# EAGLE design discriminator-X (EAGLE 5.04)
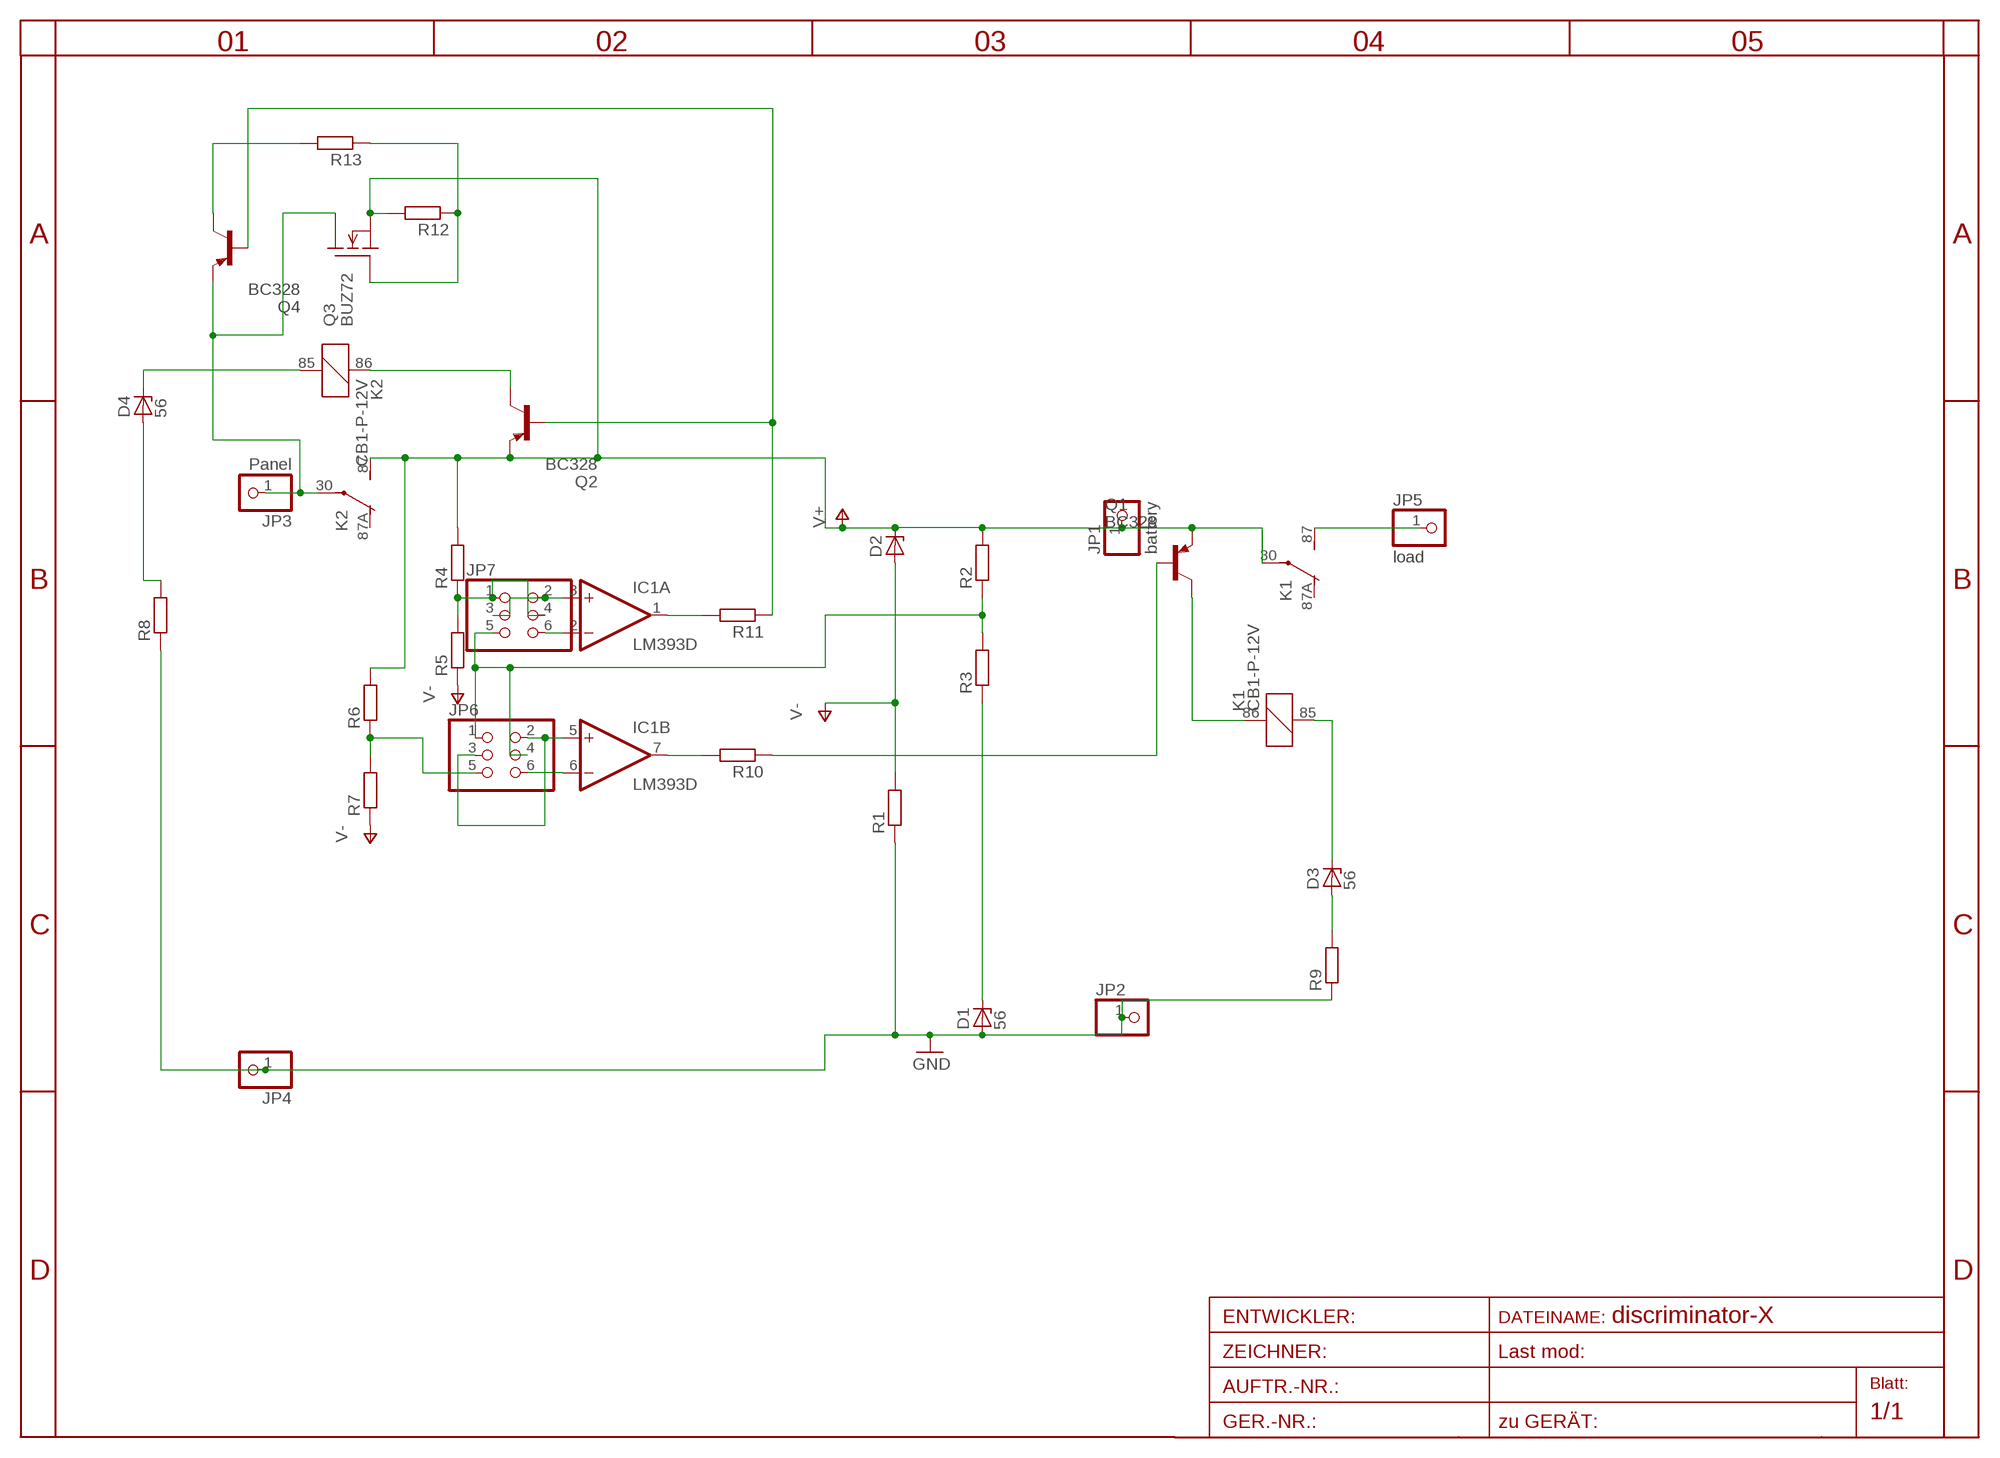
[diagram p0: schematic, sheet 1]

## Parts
D1  56  ZENER-DIODEDO35Z10  [DO35Z10]
D2  ZENER-DIODEDO35Z10  [DO35Z10]
D3  56  ZENER-DIODEDO35Z10  [DO35Z10]
D4  56  ZENER-DIODEDO35Z10  [DO35Z10]
IC1  LM393D  [SO08]
JP1  battery  PINHD-1X1  [1X01]
JP2  PINHD-1X1  [1X01]
JP3  Panel  PINHD-1X1  [1X01]
JP4  PINHD-1X1  [1X01]
JP5  load  PINHD-1X1  [1X01]
JP6  PINHD-2X3  [2X03]
JP7  PINHD-2X3  [2X03]
K1  CB1-P-12V  [CB1]
K2  CB1-P-12V  [CB1]
Q1  BC328  [TO92-EBC]
Q2  BC328  [TO92-EBC]
Q3  BUZ72  [TO220]
Q4  BC328  [TO92-EBC]
R1  R-EU_0204/7  [0204/7]
R2  R-EU_0204/7  [0204/7]
R3  R-EU_0204/7  [0204/7]
R4  R-EU_0204/7  [0204/7]
R5  R-EU_0204/7  [0204/7]
R6  R-EU_0204/7  [0204/7]
R7  R-EU_0204/7  [0204/7]
R8  R-EU_0204/7  [0204/7]
R9  R-EU_0204/7  [0204/7]
R10  R-EU_0204/7  [0204/7]
R11  R-EU_0204/7  [0204/7]
R12  R-EU_0204/7  [0204/7]
R13  R-EU_0204/7  [0204/7]

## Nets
GND: D1.A JP2.1 JP4.1 R1.1 R8.1 R9.1
LOAD: JP5.1 K1.87(2:S)
N$1: D1.C R3.1
N$2: IC1.3(A:+IN) JP7.2 JP7.3
N$3: IC1.5(B:+IN) JP6.2 JP6.3
N$4: JP6.1 JP6.4 JP7.5 R2.1 R3.2
N$5: K1.86 Q1.C
N$6: D3.C K1.85
N$7: D3.A R9.2
N$8: K2.86 Q2.C
N$9: D4.C K2.85
N$10: D4.A R8.2
N$11: IC1.6(B:-IN) JP6.6
N$12: JP6.5 R6.1 R7.2
N$13: JP7.1 JP7.4 R4.1 R5.2
N$14: IC1.1(A:OUT) R11.2
N$15: IC1.7(B:OUT) R10.2
N$16: Q2.B Q4.B R11.1
N$17: Q1.B R10.1
N$19: Q3.1(G) R12.1 R13.1
N$20: Q4.C R13.2
N$22: IC1.2(A:-IN) JP7.6
PANEL: JP3.1 K2.30(2:P) Q3.2(D) Q4.E
V+: D2.C JP1.1 K1.30(2:P) K2.87(2:S) Q1.E Q2.E Q3.3(S) R2.2 R4.2 R6.2 R12.2
V-: D2.A R1.2 R5.1 R7.1
Unconnected: K1.87A(2:O) K2.87A(2:O)

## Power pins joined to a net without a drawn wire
V+: IC1.8(P:V+)
V-: IC1.4(P:V-)

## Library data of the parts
D1-D4 = diode-1:ZENER-DIODE: Z-Diode
IC1 = linear:LM393: COMPARATOR
JP1-JP5 = pinhead:PINHD-1X1: PIN HEADER
JP6 JP7 = pinhead(2):PINHD-2X3: PIN HEADER
K1 K2 = relay:CB1*: HIGH POWER AUTOMOTIVE RELAY Form C NAiS Source: http://www.mew-europe.com/.. en_ds_61202_0000.pdf
Q1 Q2 Q4 = transistor-pnp:BC328*: PNP Transistror
Q3 = transistor-fet:BUZ72: N-Channel Enhancement MOSFET 100V; 10A; 0,2Ohm
R1-R13 = rcl-2:R-EU_: RESISTOR, European symbol

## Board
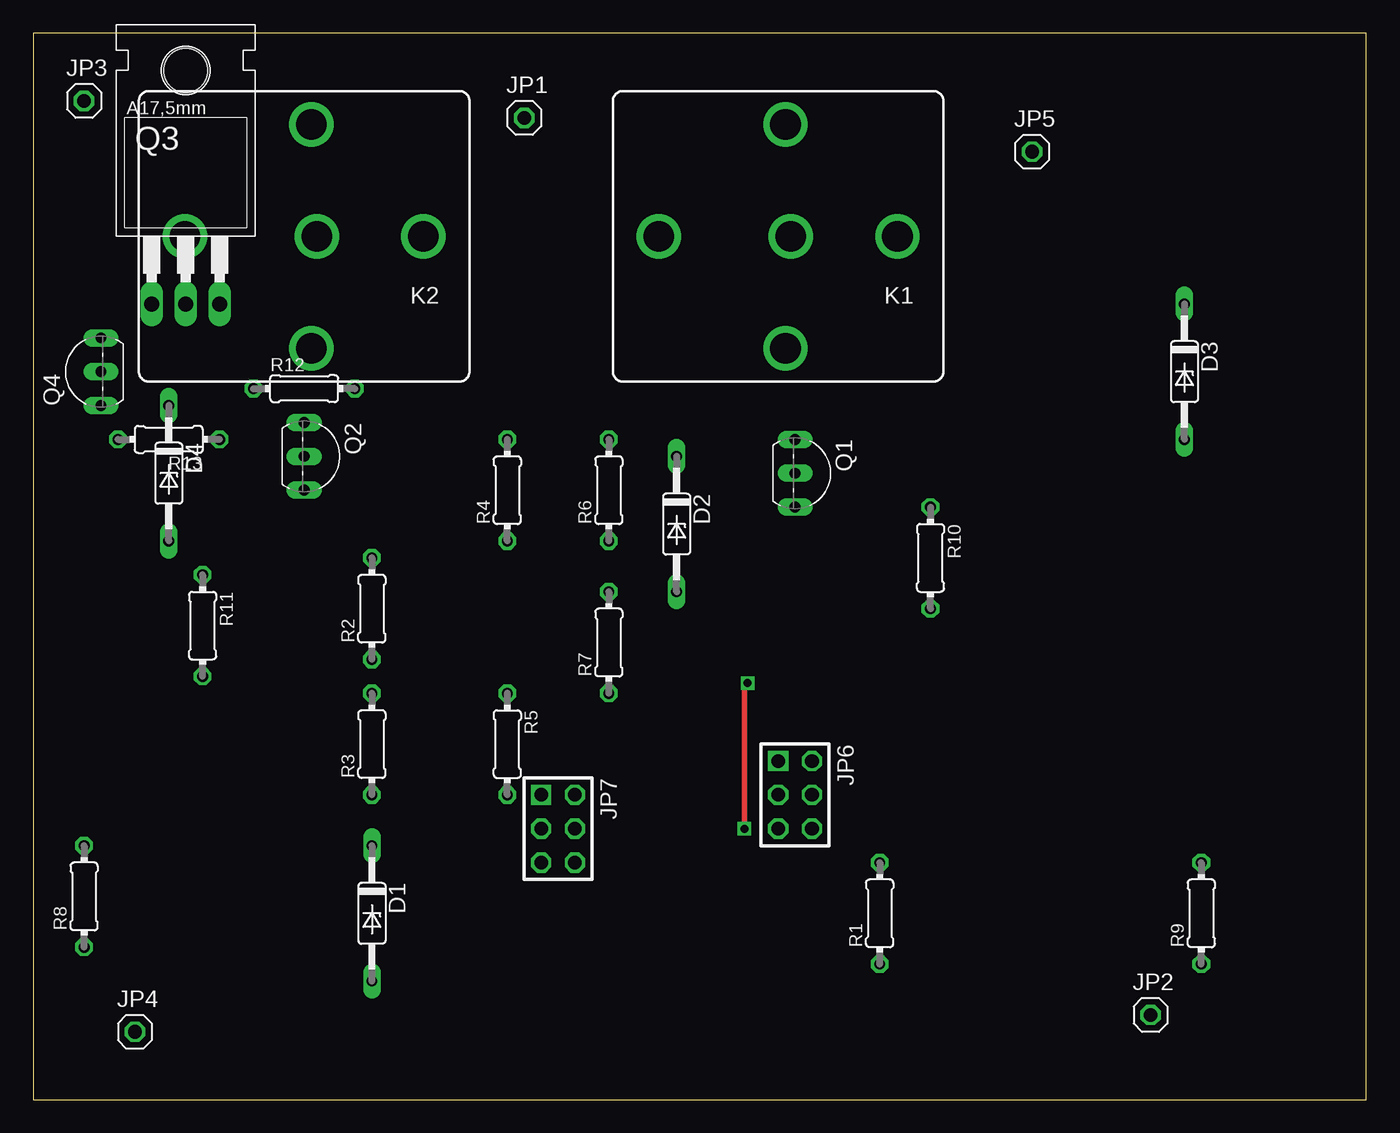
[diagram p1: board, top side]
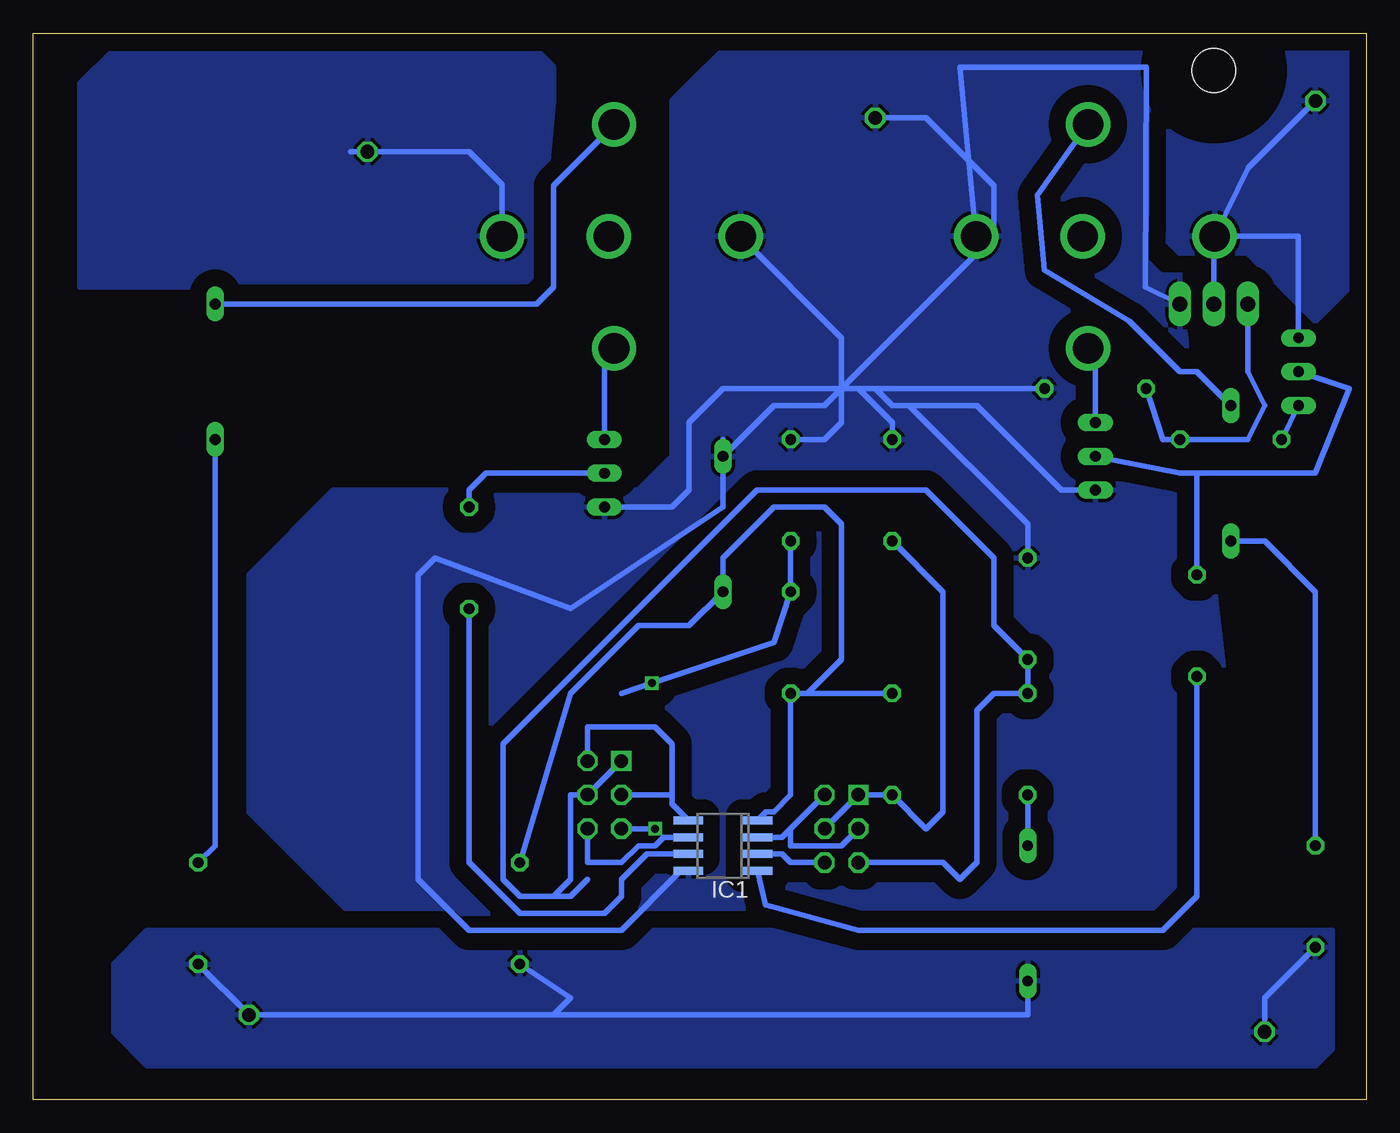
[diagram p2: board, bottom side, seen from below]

Size 100 x 80 mm. Coordinates in mm from the lower left corner, seen from the top.
Outline: 0,0 100,0 100,80 0,80 0,0
Copper layers (1*16): Top 0.035mm / dielectric 1.5mm / Bottom 0.035mm
Design rules "default": minimum track width 10mil, minimum drill 24mil, track to track 8mil, track to pad 8mil, pad to pad 8mil, via to via 8mil, smd to smd 8mil, copper to edge 40mil, drill to drill 8mil, minimum pad ring 10mil, minimum via ring 8mil, stop-mask expansion 4mil, vias tented up to drill 0mil, thermal gap 10mil

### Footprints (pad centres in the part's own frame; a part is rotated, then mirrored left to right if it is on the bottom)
DO35Z10 = drill 0.813 long: A 5.08,0; C -5.08,0
SO08 = smd 0.6 x 2.2: 1 -1.905,-2.6; 2 -0.635,-2.6; 3 0.635,-2.6; 4 1.905,-2.6; 5 1.905,2.6; 6 0.635,2.6; 7 -0.635,2.6; 8 -1.905,2.6
1X01 = drill 1.016 octagon: 1 0,0
2X03 = drill 1.016 square: 1 -2.54,-1.27 | drill 1.016 octagon: 2 -2.54,1.27; 3 0,-1.27; 4 0,1.27; 5 2.54,-1.27; 6 2.54,1.27
CB1 = drill 2.3 round: 30 8.95,0; 85 -0.55,-8.4; 86 -0.55,8.4; 87 -8.95,0; 87A -0.95,0
TO92-EBC = drill 0.813 long: B 0,-1.27; C -2.54,-1.27; E 2.54,-1.27
TO220 = drill 1.118 long: 1 -2.54,-6.35; 2 0,-6.35; 3 2.54,-6.35 | hole 3.302: 0,11.176
0204/7 = drill 0.813 octagon: 1 -3.81,0; 2 3.81,0

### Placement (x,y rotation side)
D1  25.4,13.97 270 top
D2  48.26,43.18 270 top
D3  86.36,54.61 270 top
D4  10.16,46.99 270 top
IC1  48.26,19.05 90 bottom
JP1  36.83,73.66 0 top
JP2  83.82,6.35 0 top
JP3  3.81,74.93 0 top
JP4  7.62,5.08 0 top
JP5  74.93,71.12 0 top
JP6  57.15,22.86 270 top
JP7  39.37,20.32 270 top
K1  55.88,64.77 180 top
K2  20.32,64.77 180 top
Q1  58.42,46.99 270 top
Q2  21.59,48.26 270 top
Q3  11.43,66.04 0 top
Q4  3.81,54.61 90 top
R1  63.5,13.97 90 top
R2  25.4,36.83 90 top
R3  25.4,26.67 90 top
R4  35.56,45.72 90 top
R5  35.56,26.67 270 top
R6  43.18,45.72 90 top
R7  43.18,34.29 90 top
R8  3.81,15.24 90 top
R9  87.63,13.97 90 top
R10  67.31,40.64 270 top
R11  12.7,35.56 270 top
R12  20.32,53.34 0 top
R13  10.16,49.53 180 top

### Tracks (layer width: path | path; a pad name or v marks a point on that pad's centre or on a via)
GND
  Bottom 0.406: R9.1 JP2.1 62.23,6.35 | 62.23,6.35 60.96,6.35 59.69,7.62 R1.1 | D1.A 25.4,6.35 62.23,6.35 | JP4.1 7.62,7.62 R8.1
  pour Bottom (isolate 1.27, rank 4): 2.54,12.7 91.44,12.7 93.98,10.16 93.98,5.08 91.44,2.54 3.81,2.54 2.54,3.81
LOAD
  Bottom 0.406: K1.87 64.83,68.64 67.31,71.12 JP5.1 76.2,71.12
  pour Bottom (isolate 1.27, rank 4): 60.96,74.93 60.96,77.47 62.23,78.74 93.98,78.74 96.52,76.2 96.52,60.96 62.23,60.96
N$1
  Bottom 0.406: D1.C R3.1
N$2
  Bottom 0.406: 43.18,20.32 43.81,19.68 IC1.3 | 43.18,20.32 JP7.2 | JP7.3 39.37,19.05 43.18,19.05 43.18,20.32
N$3
  Bottom 0.406: JP6.2 58.42,27.94 53.34,27.94 52.07,26.67 52.07,22.86 | 52.07,22.86 52.07,22.16 IC1.5 | 52.07,22.86 JP6.3
N$4
  Bottom 0.406: JP7.5 31.75,17.78 30.48,16.51 29.21,17.78 29.21,29.21 27.94,30.48 R3.2 R2.1 27.94,35.56 27.94,40.64 33.02,45.72 45.72,45.72 64.77,26.67 64.77,16.51 63.5,15.24 60.96,15.24 | 58.42,16.51 59.69,15.24 60.96,15.24 | JP6.1 JP6.4 59.69,22.86 59.69,16.51 60.96,15.24
N$5
  Bottom 0.406: Q1.C 57.15,55.65 K1.86
N$6
  Bottom 0.406: K1.85 56.43,73.11 60.96,68.58 60.96,60.96 62.23,59.69 D3.C
N$7
  Bottom 0.406: D3.A 86.36,19.05 R9.2
N$8
  Bottom 0.406: Q2.C 20.32,55.65 K2.86
N$9
  Bottom 0.406: K2.85 24.68,67.86 24.13,62.23 17.78,58.42 13.97,54.61 12.7,54.61 D4.C
N$10
  Bottom 0.406: R8.2 3.81,38.1 7.62,41.91 D4.A
N$11
  Bottom 0.406: JP6.6 58.42,17.78 55.88,17.78 54.61,19.05 53.34,19.05 52.7,19.68 IC1.6
N$12  (via drill 0.6)
  Top 0.406: v53.34,20.32 53.34,30.99 v53.59,31.24
  Bottom 0.406: 53.21,31.37 44.45,34.29 R7.2 R6.1 | v53.59,31.24 53.21,31.37 | v53.59,31.24 55.88,30.48 | v53.34,20.32 JP6.5 | v53.59,31.24 53.34,31.24 53.21,31.37
N$13
  Bottom 0.406: R4.1 31.75,38.1 31.75,21.59 33.02,20.32 R5.2 JP7.1 JP7.4
N$14
  Bottom 0.406: IC1.1 45.09,14.61 38.1,12.7 15.24,12.7 12.7,15.24 R11.2
N$15
  Bottom 0.406: IC1.7 53.98,18.41 55.88,16.51 55.88,15.24 57.15,13.97 63.5,13.97 67.31,17.78 R10.2
N$16
  Bottom 0.406: 13.97,46.99 Q2.B | 13.97,46.99 12.7,46.99 R11.1 | 13.97,46.99 3.81,46.99 1.27,53.34 Q4.B
N$17
  Bottom 0.406: Q1.B 66.04,46.99 67.31,45.72 R10.1
N$19
  Bottom 0.406: Q3.1 8.89,54.61 7.62,52.07 8.89,49.53 15.24,49.53 | 15.24,49.53 R12.1 | 15.24,49.53 R13.1
N$20
  Bottom 0.406: R13.2 Q4.C
N$22
  Bottom 0.406: JP7.6 43.18,17.78 43.81,18.41 IC1.2
PANEL
  Bottom 0.406: K2.30 8.83,69.91 JP3.1 | K2.30 11.43,64.77 Q3.2 | K2.30 5.08,64.77 Q4.E
  pour Bottom (isolate 1.27): 0,80.01 0,62.23 3.81,58.42 8.89,63.5 12.7,63.5 13.97,63.5 15.24,64.77 15.24,80.01
V+
  Bottom 0.406: IC1.8 51.44,17.14 55.88,12.7 67.31,12.7 71.12,16.51 71.12,39.37 69.85,40.64 59.69,36.83 48.26,44.45 D2.C | D2.C 44.45,52.07 40.64,52.07 39.37,53.34 | 39.37,53.34 39.37,57.15 46.99,64.77 K1.30 | R6.2 40.64,49.53 39.37,50.8 39.37,53.34 | R4.2 35.56,50.8 38.1,53.34 | Q2.E 22.86,45.72 29.21,52.07 34.29,52.07 | 34.29,52.07 35.56,52.07 36.83,53.34 38.1,53.34 | 38.1,53.34 39.37,53.34 | R2.2 25.4,43.18 34.29,52.07 | K2.87 27.94,64.77 39.37,53.34 | JP1.1 33.02,73.66 27.94,68.58 27.94,64.83 K2.87 | 39.37,53.34 48.26,53.34 50.8,50.8 50.8,45.72 52.07,44.45 Q1.E | D2.C 48.26,49.53 | Q3.3 16.57,60.96 16.51,77.47 30.48,77.47 K2.87 | 38.1,53.34 R12.2
  pour Bottom (isolate 1.27, rank 5): 13.97,60.96 13.97,77.47 16.51,80.01 46.99,80.01 52.07,74.93 52.07,48.26 54.61,45.72 77.47,45.72 83.82,39.37 83.82,21.59 76.2,13.97 11.43,13.97 8.89,16.51
V-
  Bottom 0.406: R7.1 41.91,30.48 39.37,33.02 39.37,43.18 40.64,44.45 44.45,44.45 48.26,40.64 D2.A 50.8,35.56 54.61,35.56 59.69,30.48 R1.2 | R7.1 R5.1 | R7.1 43.18,22.86 44.45,21.59 45.02,21.59 IC1.4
